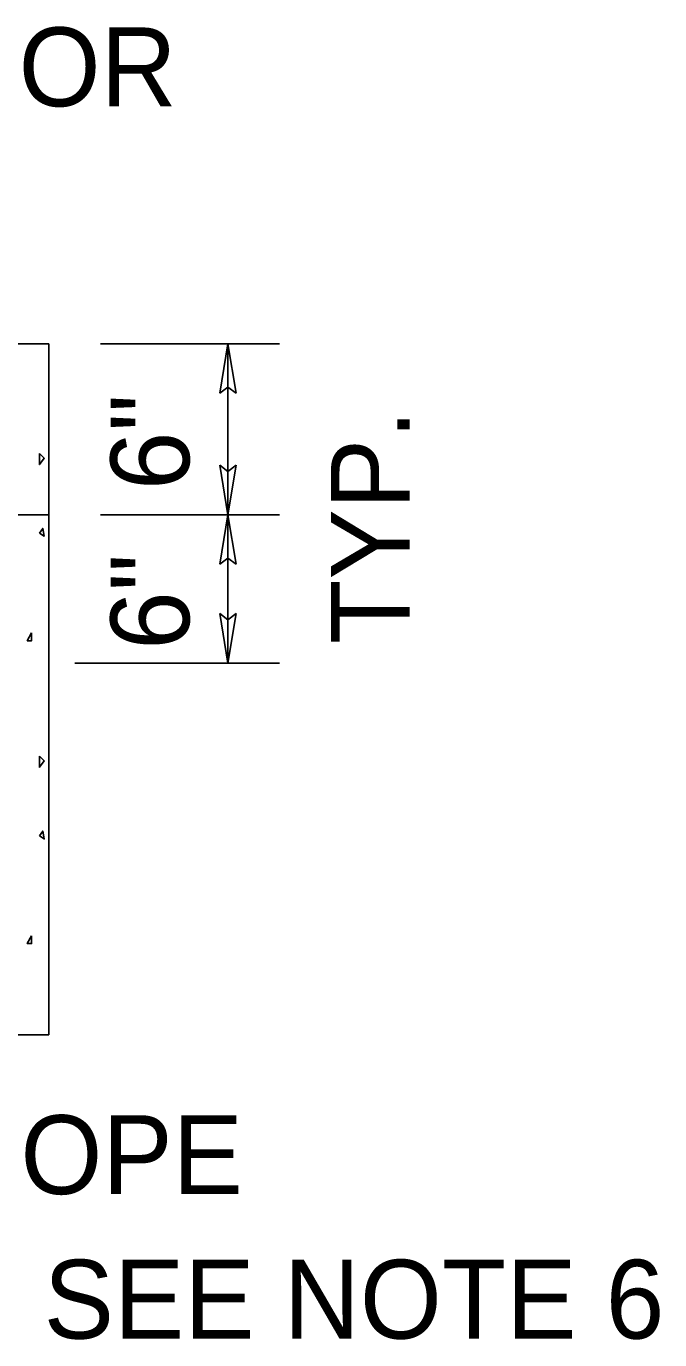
# Model space of a CAD drawing. Extents: x 5.8 to 18, y -5.2 to 5.4.
# Drawn here: x 8.641 to 9.123, y -0.572 to 0.427 of the extents above; entities that cross this region are included whole.
import ezdxf

# ---------------------------------------------------------------- set-up
doc = ezdxf.new("R2010")
doc.units = 0
for name, color, linetype in [('DETL-DIMS', 7, 'Continuous'), ('DETL-LINE', 7, 'Continuous'), ('DETL-NOTE', 7, 'Continuous'), ('DETL-PATT', 7, 'Continuous')]:
    doc.layers.add(name, color=color, linetype=linetype)

msp = doc.modelspace()

# ---------------------------------------------------------------- linework, layer by layer
at = {"layer": 'DETL-DIMS'}
for p, q in [((8.69725, 0.18564), (8.83353, 0.18564)), ((8.78804, 0.148), (8.79431, 0.18564)), ((8.79431, 0.05545), (8.79431, 0.18564)), ((8.80059, 0.148), (8.79431, 0.18564)), ((8.78804, 0.148), (8.79431, 0.1527)), ((8.80059, 0.148), (8.79431, 0.1527)), ((8.78804, 0.09309), (8.79431, 0.05545)), ((8.78804, 0.09309), (8.79431, 0.08839)), ((8.80059, 0.09309), (8.79431, 0.05545)), ((8.80059, 0.09309), (8.79431, 0.08839)), ((8.69725, 0.05545), (8.83353, 0.05545)), ((8.78804, 0.0178), (8.79431, 0.05545)), ((8.79431, -0.05742), (8.79431, 0.05545)), ((8.80059, 0.0178), (8.79431, 0.05545)), ((8.78804, 0.0178), (8.79431, 0.02251)), ((8.80059, 0.0178), (8.79431, 0.02251)), ((8.78804, -0.01977), (8.79431, -0.05742)), ((8.78804, -0.01977), (8.79431, -0.02448)), ((8.80059, -0.01977), (8.79431, -0.05742)), ((8.80059, -0.01977), (8.79431, -0.02448)), ((8.67765, -0.05742), (8.83353, -0.05742))]:
    msp.add_line(p, q, dxfattribs=at)
at = {"layer": 'DETL-LINE'}
for p, q in [((6.26486, 0.18564), (8.65804, 0.18564)), ((8.65804, -0.34028), (8.65804, 0.18564)), ((6.26243, 0.05545), (8.65804, 0.05545)), ((7.03698, -0.34028), (8.65804, -0.34028))]:
    msp.add_line(p, q, dxfattribs=at)
at = {"layer": 'DETL-PATT'}
for points in [[(8.65075, 0.10219), (8.65075, 0.09372), (8.65443, 0.09851)], [(8.65075, 0.04149), (8.65443, 0.03921), (8.65329, 0.04513)], [(8.64482, -0.03448), (8.64145, -0.0404), (8.64482, -0.0404)], [(8.65075, -0.12824), (8.65075, -0.13671), (8.65443, -0.13189)], [(8.65075, -0.18895), (8.65443, -0.19118), (8.65329, -0.18526)], [(8.64482, -0.26487), (8.64145, -0.27083), (8.64482, -0.27083)]]:
    msp.add_lwpolyline(points, close=True, dxfattribs=at)

# ---------------------------------------------------------------- texts
at = {"layer": 'DETL-NOTE'}
for s, p in [('SLOPED TROUGH FLOOR', (7.76114, 0.36635)), ('GRADE AND SLOPE', (8.03886, -0.46153)), ('ADJUSTMENTS SEE NOTE 6', (8.03886, -0.57153))]:
    msp.add_text(s, height=0.06, dxfattribs=at).set_placement(p)
for s, p in [('6"', (8.7649, 0.07419)), ('TYP.', (8.93275, -0.04283)), ('6"', (8.7649, -0.04734))]:
    msp.add_text(s, height=0.06, rotation=90, dxfattribs=at).set_placement(p)

doc.saveas('drawing.dxf')
